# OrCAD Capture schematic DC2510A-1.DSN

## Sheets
1 PAGE2: size Custom
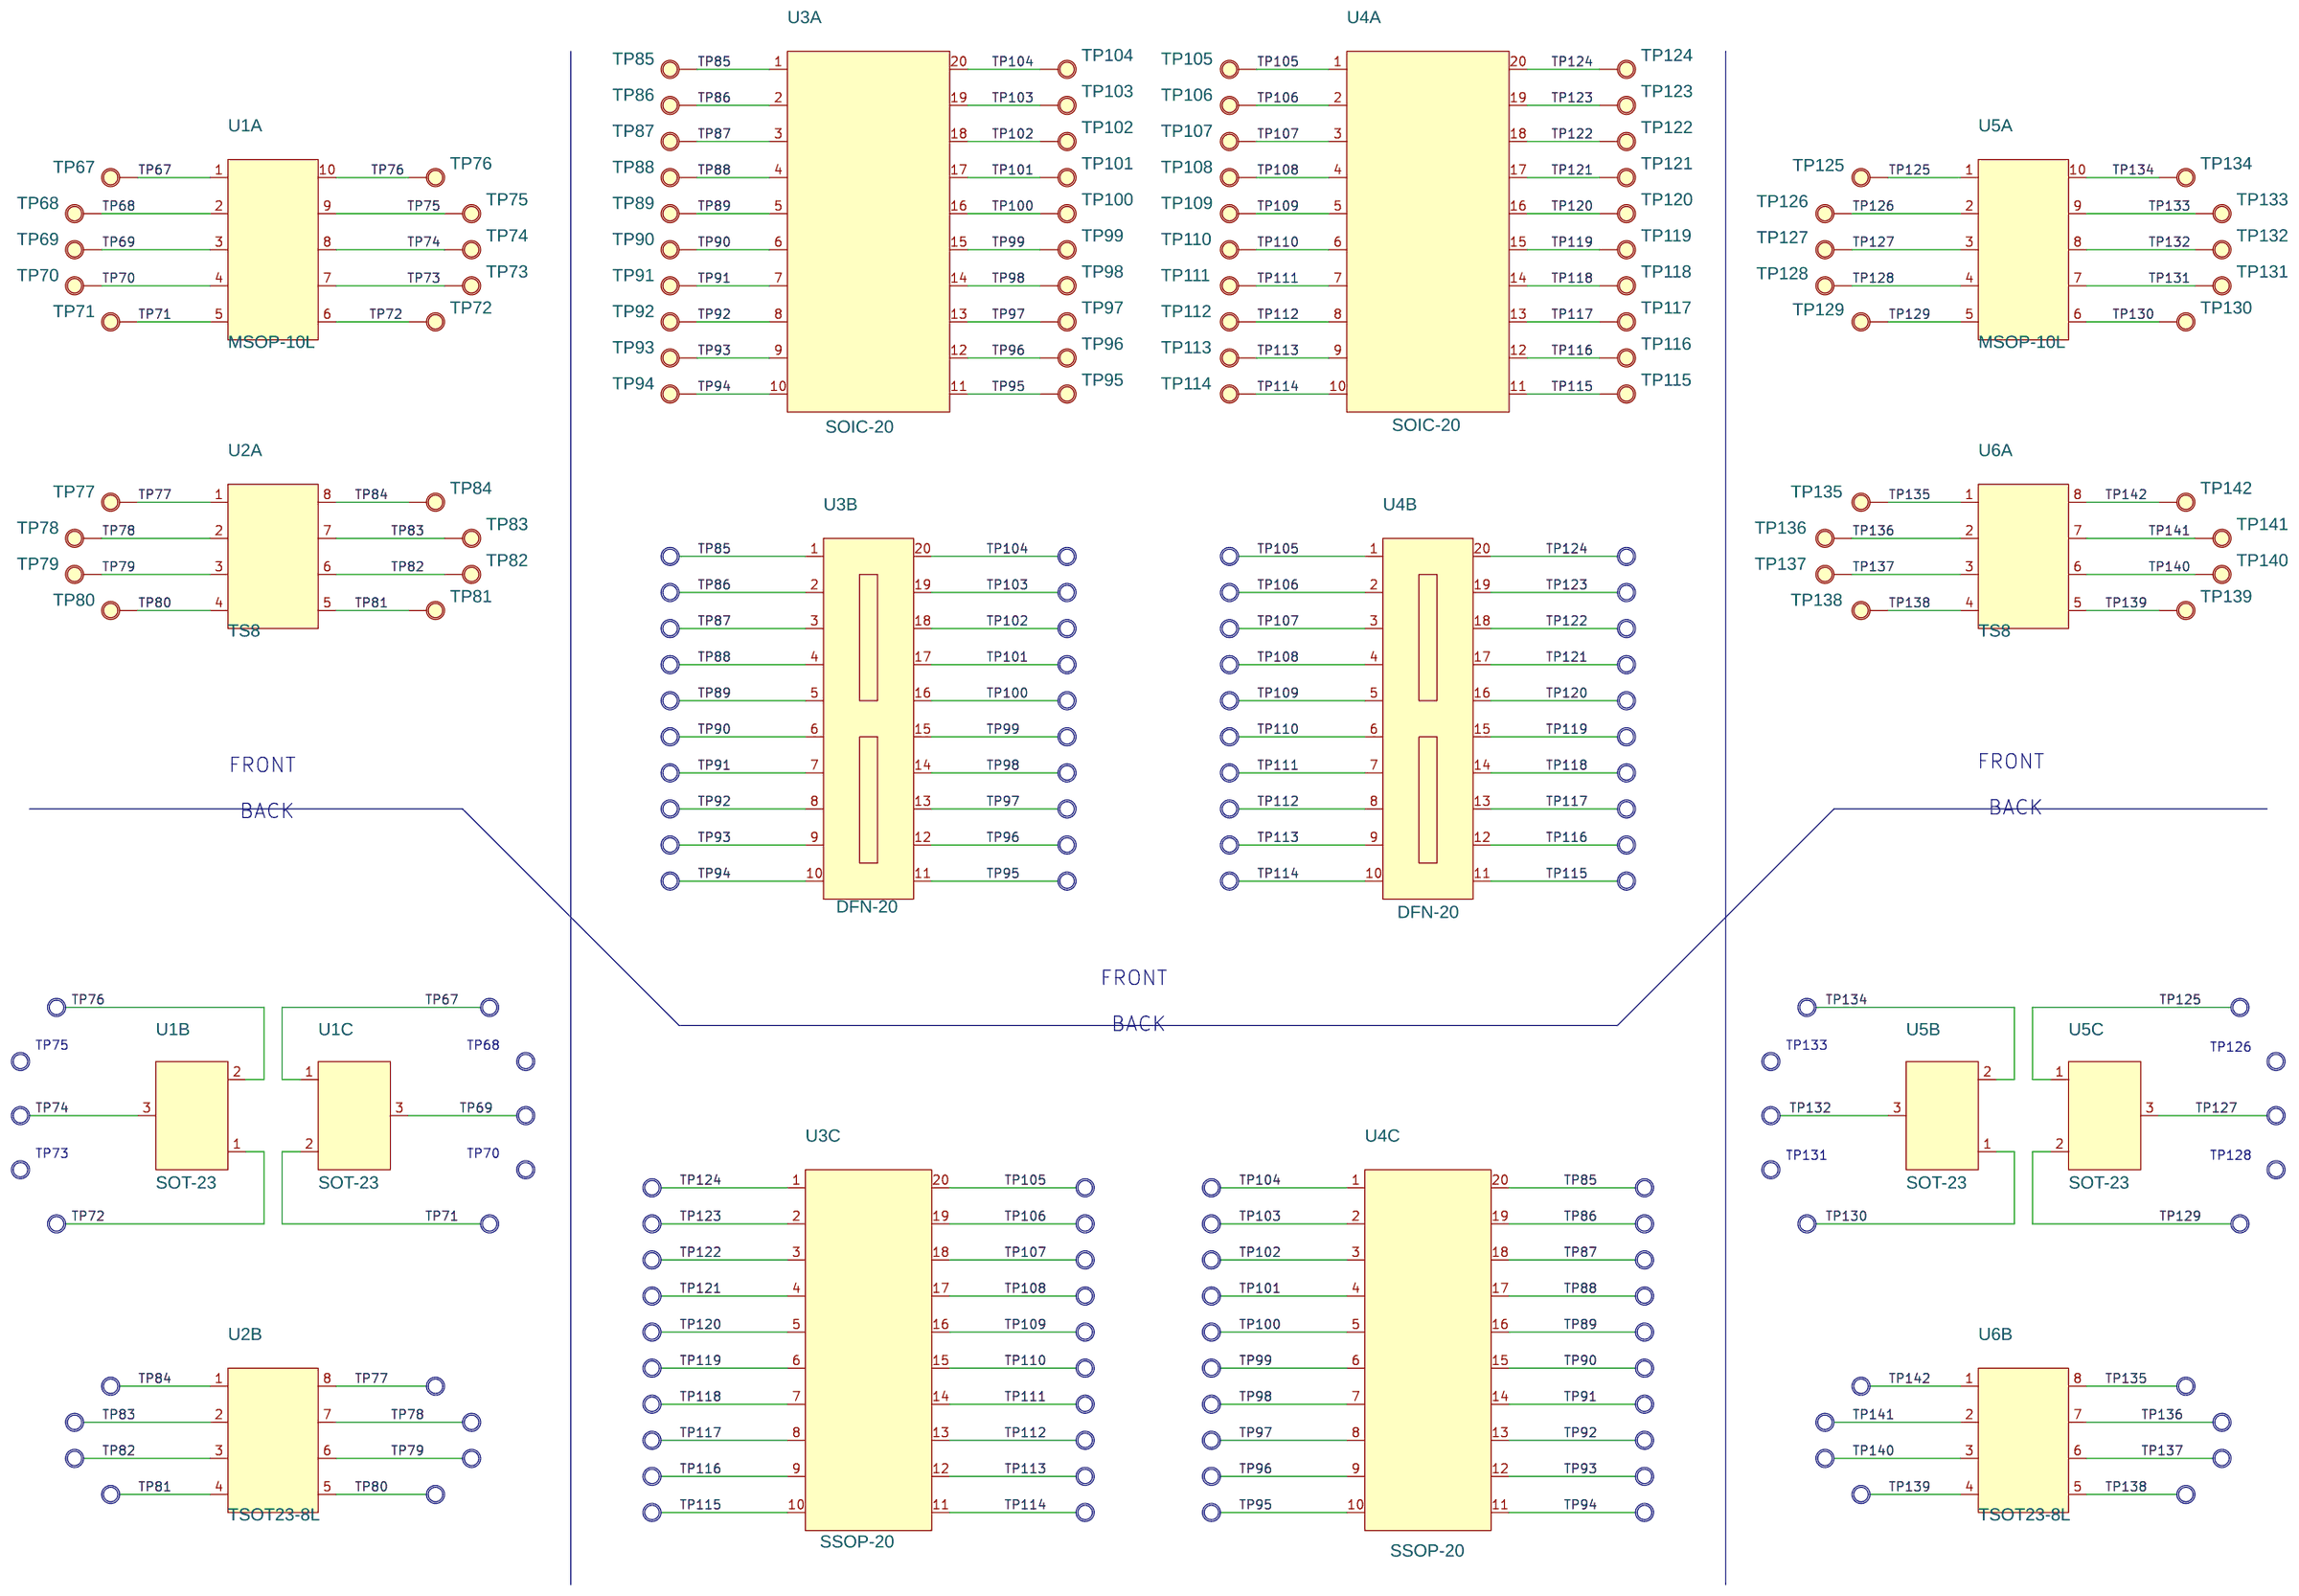
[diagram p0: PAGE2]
2 PAGE1: size Custom; title: DC2510A: SHIELD BOARD; rev: 1; note: DEMO CIRCUIT 2510A
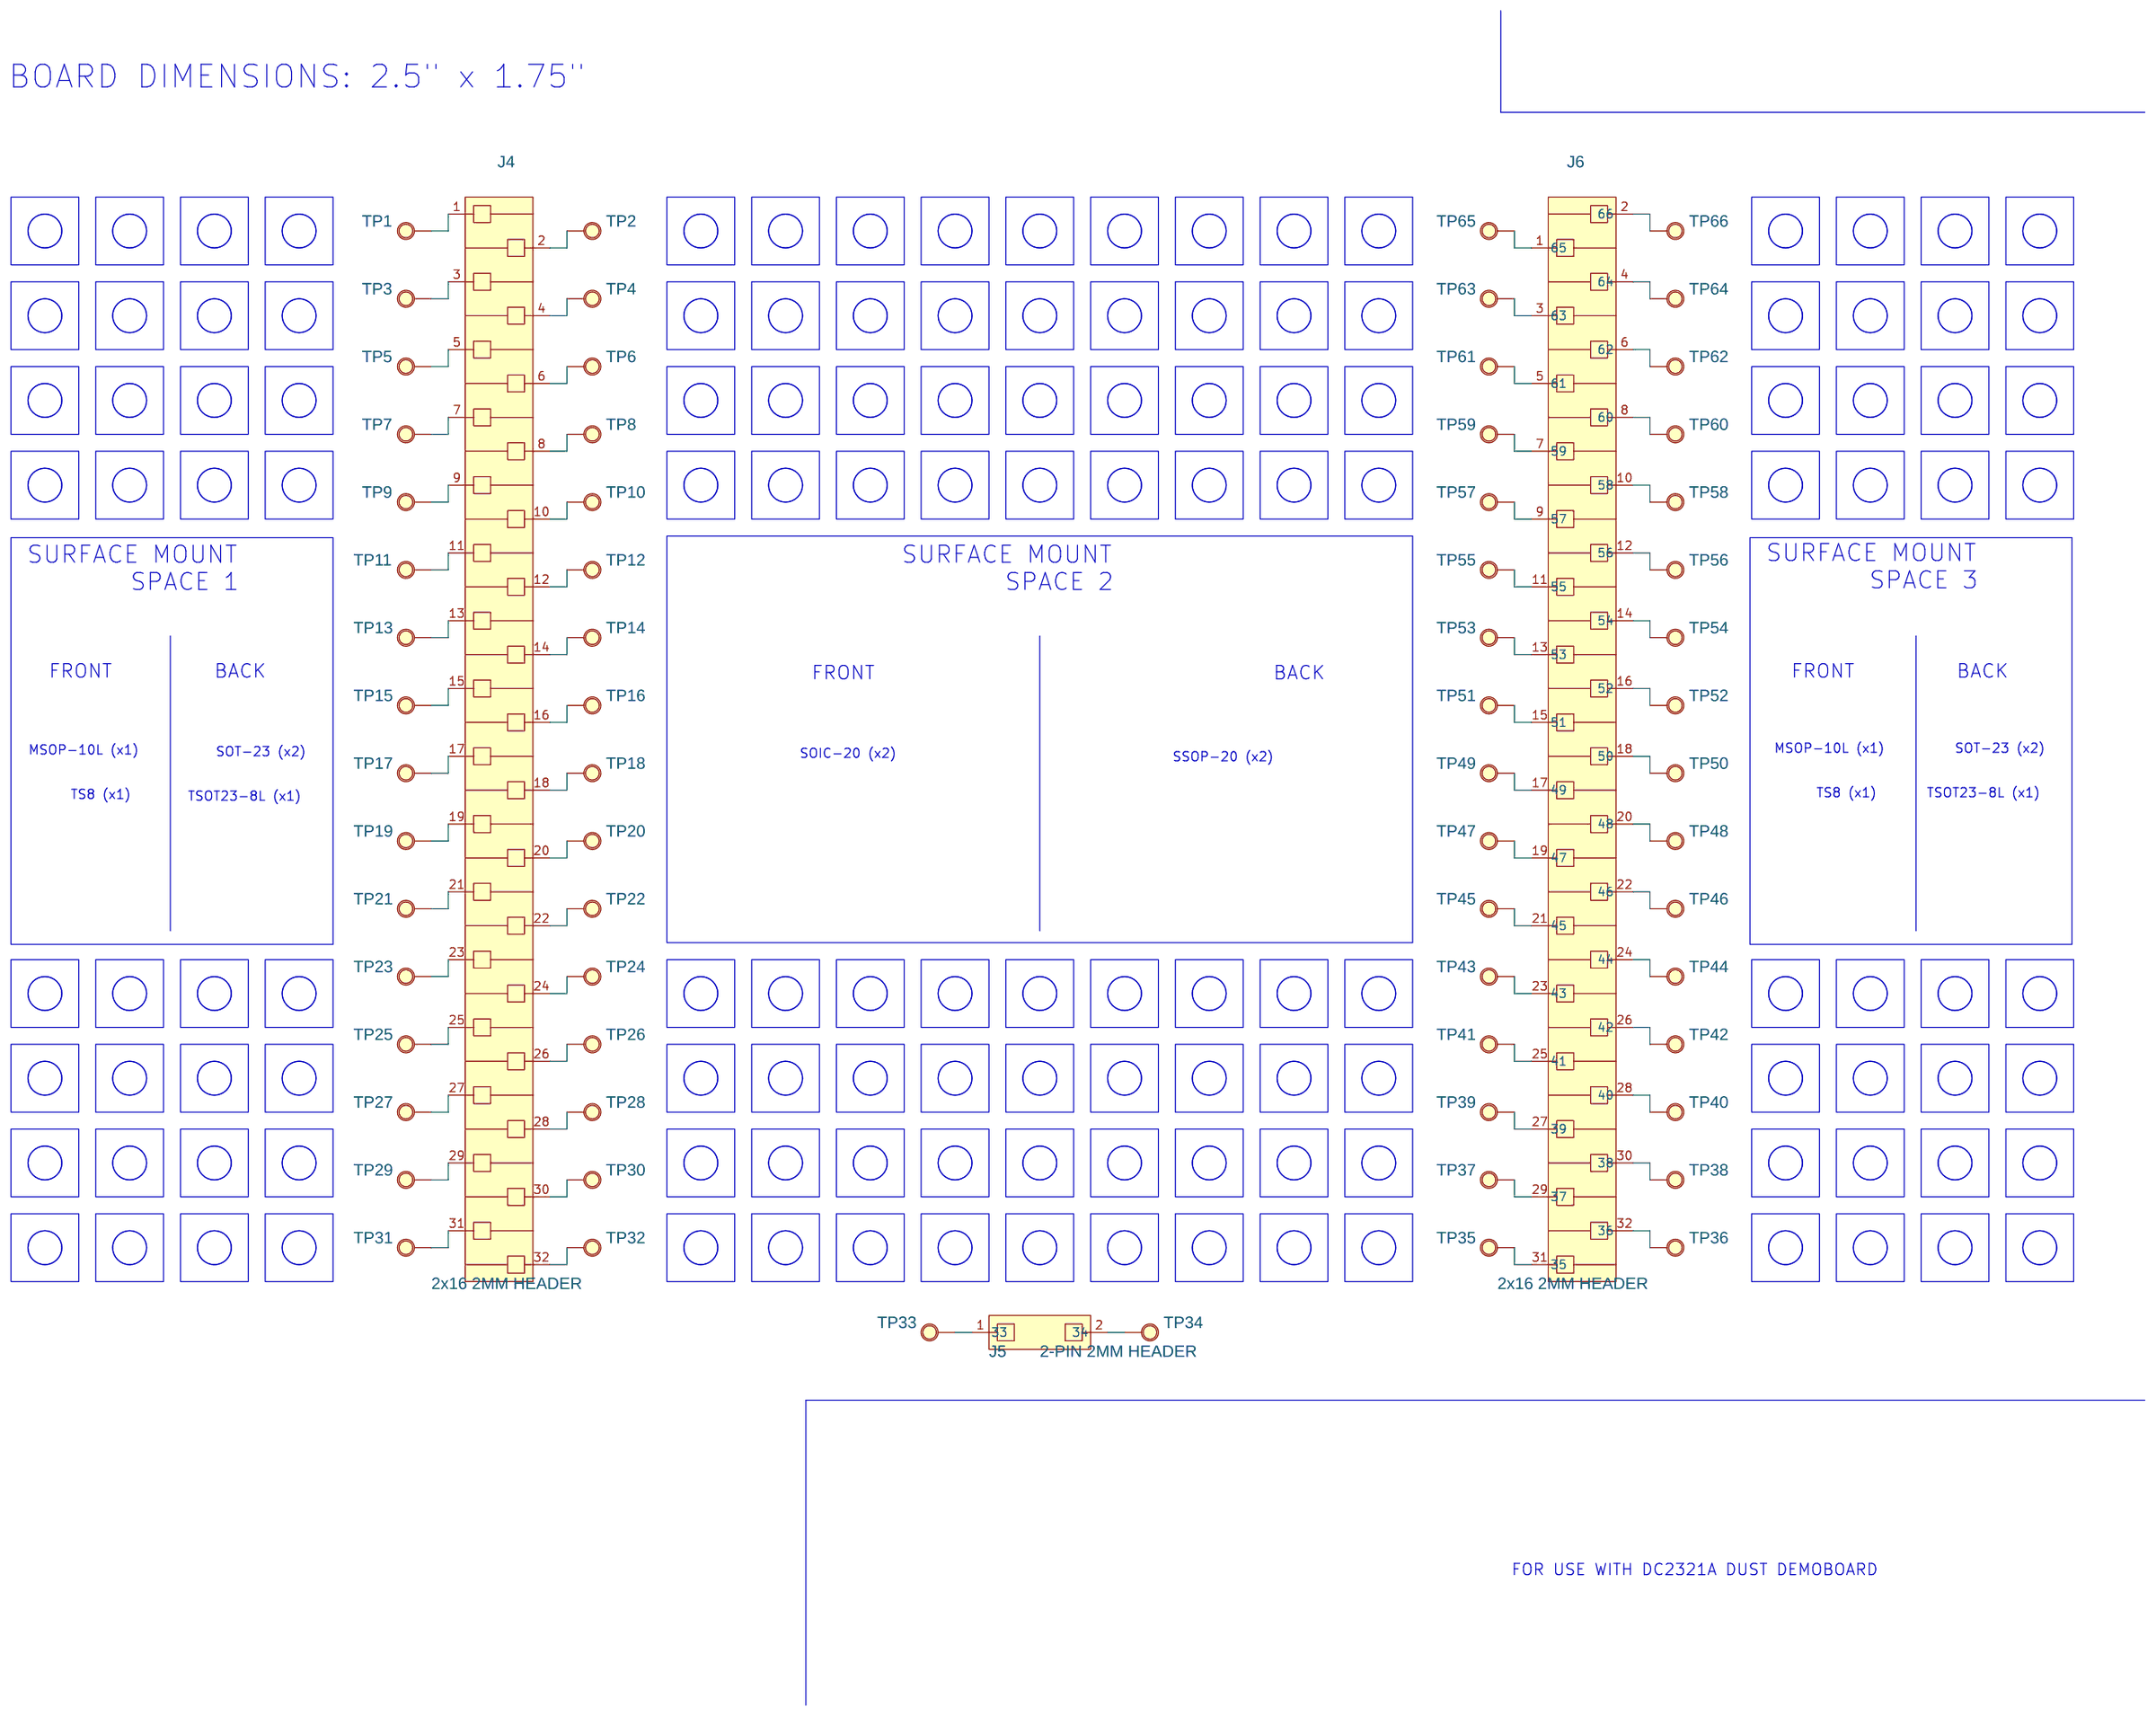
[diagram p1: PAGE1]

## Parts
sheet PAGE1
J4  2x16 2MM HEADER  [HDR-WURTH-62003221821-2X16-2MM]
J5  2-PIN 2MM HEADER  [WURTH-62000211821-2P-2MM]
J6  2x16 2MM HEADER  [HDR-WURTH-62003221821-2X16-2MM]
TP1  Large Turret_1  [TP]
TP2  Large Turret_1  [TP]
TP3  Large Turret_1  [TP]
TP4  Large Turret_1  [TP]
TP5  Large Turret_1  [TP]
TP6  Large Turret_1  [TP]
TP7  Large Turret_1  [TP]
TP8  Large Turret_1  [TP]
TP9  Large Turret_1  [TP]
TP10  Large Turret_1  [TP]
TP11  Large Turret_1  [TP]
TP12  Large Turret_1  [TP]
TP13  Large Turret_1  [TP]
TP14  Large Turret_1  [TP]
TP15  Large Turret_1  [TP]
TP16  Large Turret_1  [TP]
TP17  Large Turret_1  [TP]
TP18  Large Turret_1  [TP]
TP19  Large Turret_1  [TP]
TP20  Large Turret_1  [TP]
TP21  Large Turret_1  [TP]
TP22  Large Turret_1  [TP]
TP23  Large Turret_1  [TP]
TP24  Large Turret_1  [TP]
TP25  Large Turret_1  [TP]
TP26  Large Turret_1  [TP]
TP27  Large Turret_1  [TP]
TP28  Large Turret_1  [TP]
TP29  Large Turret_1  [TP]
TP30  Large Turret_1  [TP]
TP31  Large Turret_1  [TP]
TP32  Large Turret_1  [TP]
TP33  Large Turret_1  [TP]
TP34  Large Turret_1  [TP]
TP35  Large Turret_1  [TP]
TP36  Large Turret_1  [TP]
TP37  Large Turret_1  [TP]
TP38  Large Turret_1  [TP]
TP39  Large Turret_1  [TP]
TP40  Large Turret_1  [TP]
TP41  Large Turret_1  [TP]
TP42  Large Turret_1  [TP]
TP43  Large Turret_1  [TP]
TP44  Large Turret_1  [TP]
TP45  Large Turret_1  [TP]
TP46  Large Turret_1  [TP]
TP47  Large Turret_1  [TP]
TP48  Large Turret_1  [TP]
TP49  Large Turret_1  [TP]
TP50  Large Turret_1  [TP]
TP51  Large Turret_1  [TP]
TP52  Large Turret_1  [TP]
TP53  Large Turret_1  [TP]
TP54  Large Turret_1  [TP]
TP55  Large Turret_1  [TP]
TP56  Large Turret_1  [TP]
TP57  Large Turret_1  [TP]
TP58  Large Turret_1  [TP]
TP59  Large Turret_1  [TP]
TP60  Large Turret_1  [TP]
TP61  Large Turret_1  [TP]
TP62  Large Turret_1  [TP]
TP63  Large Turret_1  [TP]
TP64  Large Turret_1  [TP]
TP65  Large Turret_1  [TP]
TP66  Large Turret_1  [TP]
sheet PAGE2
TP67  Large Turret_1  [PAD060/035]
TP68  Large Turret_1  [PAD060/035]
TP69  Large Turret_1  [PAD060/035]
TP70  Large Turret_1  [PAD060/035]
TP71  Large Turret_1  [PAD060/035]
TP72  Large Turret_1  [PAD060/035]
TP73  Large Turret_1  [PAD060/035]
TP74  Large Turret_1  [PAD060/035]
TP75  Large Turret_1  [PAD060/035]
TP76  Large Turret_1  [PAD060/035]
TP77  Large Turret_1  [PAD060/035]
TP78  Large Turret_1  [PAD060/035]
TP79  Large Turret_1  [PAD060/035]
TP80  Large Turret_1  [PAD060/035]
TP81  Large Turret_1  [PAD060/035]
TP82  Large Turret_1  [PAD060/035]
TP83  Large Turret_1  [PAD060/035]
TP84  Large Turret_1  [PAD060/035]
TP85  Large Turret_1  [PAD060/035]
TP86  Large Turret_1  [PAD060/035]
TP87  Large Turret_1  [PAD060/035]
TP88  Large Turret_1  [PAD060/035]
TP89  Large Turret_1  [PAD060/035]
TP90  Large Turret_1  [PAD060/035]
TP91  Large Turret_1  [PAD060/035]
TP92  Large Turret_1  [PAD060/035]
TP93  Large Turret_1  [PAD060/035]
TP94  Large Turret_1  [PAD060/035]
TP95  Large Turret_1  [PAD060/035]
TP96  Large Turret_1  [PAD060/035]
TP97  Large Turret_1  [PAD060/035]
TP98  Large Turret_1  [PAD060/035]
TP99  Large Turret_1  [PAD060/035]
TP100  Large Turret_1  [PAD060/035]
TP101  Large Turret_1  [PAD060/035]
TP102  Large Turret_1  [PAD060/035]
TP103  Large Turret_1  [PAD060/035]
TP104  Large Turret_1  [PAD060/035]
TP105  Large Turret_1  [PAD060/035]
TP106  Large Turret_1  [PAD060/035]
TP107  Large Turret_1  [PAD060/035]
TP108  Large Turret_1  [PAD060/035]
TP109  Large Turret_1  [PAD060/035]
TP110  Large Turret_1  [PAD060/035]
TP111  Large Turret_1  [PAD060/035]
TP112  Large Turret_1  [PAD060/035]
TP113  Large Turret_1  [PAD060/035]
TP114  Large Turret_1  [PAD060/035]
TP115  Large Turret_1  [PAD060/035]
TP116  Large Turret_1  [PAD060/035]
TP117  Large Turret_1  [PAD060/035]
TP118  Large Turret_1  [PAD060/035]
TP119  Large Turret_1  [PAD060/035]
TP120  Large Turret_1  [PAD060/035]
TP121  Large Turret_1  [PAD060/035]
TP122  Large Turret_1  [PAD060/035]
TP123  Large Turret_1  [PAD060/035]
TP124  Large Turret_1  [PAD060/035]
TP125  Large Turret_1  [PAD060/035]
TP126  Large Turret_1  [PAD060/035]
TP127  Large Turret_1  [PAD060/035]
TP128  Large Turret_1  [PAD060/035]
TP129  Large Turret_1  [PAD060/035]
TP130  Large Turret_1  [PAD060/035]
TP131  Large Turret_1  [PAD060/035]
TP132  Large Turret_1  [PAD060/035]
TP133  Large Turret_1  [PAD060/035]
TP134  Large Turret_1  [PAD060/035]
TP135  Large Turret_1  [PAD060/035]
TP136  Large Turret_1  [PAD060/035]
TP137  Large Turret_1  [PAD060/035]
TP138  Large Turret_1  [PAD060/035]
TP139  Large Turret_1  [PAD060/035]
TP140  Large Turret_1  [PAD060/035]
TP141  Large Turret_1  [PAD060/035]
TP142  Large Turret_1  [PAD060/035]
U1A  MSOP-10L  [MSOP10]
U1B  SOT-23  [SOT-23]
U1C  SOT-23  [SOT-23]
U2A  TS8  [TS8]
U2B  TSOT23-8L  [TSOT23-8]
U3A  SOIC-20  [SOIC127P760X205-20L]
U3B  DFN-20  [DFN-CUSTOM-DC2510A]
U3C  SSOP-20  [SSOP20-2-MODIFIED]
U4A  SOIC-20  [SOIC127P760X205-20L]
U4B  DFN-20  [DFN-CUSTOM-DC2510A]
U4C  SSOP-20  [SSOP20-2-MODIFIED]
U5A  MSOP-10L  [MSOP10]
U5B  SOT-23  [SOT-23]
U5C  SOT-23  [SOT-23]
U6A  TS8  [TS8]
U6B  TSOT23-8L  [TSOT23-8]

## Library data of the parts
J4 = 2x16_2MM_CONNECTOR_19
J5 = 2_PIN,_2MM_PITCH,_SOCKET_9
J6 = 2x16_2MM_CONNECTOR_21
TP1-TP142 = Large_Turret_1
U1A U5A = LT1112_4
U1B U5B = LT1112_7
U1C U5C = LT1112_6
U2A U2B U6A U6B = LT1112_3
U3A = LT1112_12
U3B = LT1112_13
U3C U4C = LT1112_15
U4A = LT1112_11
U4B = LT1112_14

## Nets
TP67: TP67.1 U1A.1 U1C.1
TP68: TP68.1 U1A.2
TP69: TP69.1 U1A.3 U1C.3
TP70: TP70.1 U1A.4
TP71: TP71.1 U1A.5 U1C.2
TP72: TP72.1 U1A.6 U1B.1
TP73: TP73.1 U1A.7
TP74: TP74.1 U1A.8 U1B.3
TP75: TP75.1 U1A.9
TP76: TP76.1 U1A.10 U1B.2
TP77: TP77.1 U2A.1 U2B.8
TP78: TP78.1 U2A.2 U2B.7
TP79: TP79.1 U2A.3 U2B.6
TP80: TP80.1 U2A.4 U2B.5
TP81: TP81.1 U2A.5 U2B.4
TP82: TP82.1 U2A.6 U2B.3
TP83: TP83.1 U2A.7 U2B.2
TP84: TP84.1 U2A.8 U2B.1
TP85: TP85.1 U3A.1 U3B.1 U4C.20
TP86: TP86.1 U3A.2 U3B.2 U4C.19
TP87: TP87.1 U3A.3 U3B.3 U4C.18
TP88: TP88.1 U3A.4 U3B.4 U4C.17
TP89: TP89.1 U3A.5 U3B.5 U4C.16
TP90: TP90.1 U3A.6 U3B.6 U4C.15
TP91: TP91.1 U3A.7 U3B.7 U4C.14
TP92: TP92.1 U3A.8 U3B.8 U4C.13
TP93: TP93.1 U3A.9 U3B.9 U4C.12
TP94: TP94.1 U3A.10 U3B.10 U4C.11
TP95: TP95.1 U3A.11 U3B.11 U4C.10
TP96: TP96.1 U3A.12 U3B.12 U4C.9
TP97: TP97.1 U3A.13 U3B.13 U4C.8
TP98: TP98.1 U3A.14 U3B.14 U4C.7
TP99: TP99.1 U3A.15 U3B.15 U4C.6
TP100: TP100.1 U3A.16 U3B.16 U4C.5
TP101: TP101.1 U3A.17 U3B.17 U4C.4
TP102: TP102.1 U3A.18 U3B.18 U4C.3
TP103: TP103.1 U3A.19 U3B.19 U4C.2
TP104: TP104.1 U3A.20 U3B.20 U4C.1
TP105: TP105.1 U3C.20 U4A.1 U4B.1
TP106: TP106.1 U3C.19 U4A.2 U4B.2
TP107: TP107.1 U3C.18 U4A.3 U4B.3
TP108: TP108.1 U3C.17 U4A.4 U4B.4
TP109: TP109.1 U3C.16 U4A.5 U4B.5
TP110: TP110.1 U3C.15 U4A.6 U4B.6
TP111: TP111.1 U3C.14 U4A.7 U4B.7
TP112: TP112.1 U3C.13 U4A.8 U4B.8
TP113: TP113.1 U3C.12 U4A.9 U4B.9
TP114: TP114.1 U3C.11 U4A.10 U4B.10
TP115: TP115.1 U3C.10 U4A.11 U4B.11
TP116: TP116.1 U3C.9 U4A.12 U4B.12
TP117: TP117.1 U3C.8 U4A.13 U4B.13
TP118: TP118.1 U3C.7 U4A.14 U4B.14
TP119: TP119.1 U3C.6 U4A.15 U4B.15
TP120: TP120.1 U3C.5 U4A.16 U4B.16
TP121: TP121.1 U3C.4 U4A.17 U4B.17
TP122: TP122.1 U3C.3 U4A.18 U4B.18
TP123: TP123.1 U3C.2 U4A.19 U4B.19
TP124: TP124.1 U3C.1 U4A.20 U4B.20
TP125: TP125.1 U5A.1 U5C.1
TP126: TP126.1 U5A.2
TP127: TP127.1 U5A.3 U5C.3
TP128: TP128.1 U5A.4
TP129: TP129.1 U5A.5 U5C.2
TP130: TP130.1 U5A.6 U5B.1
TP131: TP131.1 U5A.7
TP132: TP132.1 U5A.8 U5B.3
TP133: TP133.1 U5A.9
TP134: TP134.1 U5A.10 U5B.2
TP135: TP135.1 U6A.1 U6B.8
TP136: TP136.1 U6A.2 U6B.7
TP137: TP137.1 U6A.3 U6B.6
TP138: TP138.1 U6A.4 U6B.5
TP139: TP139.1 U6A.5 U6B.4
TP140: TP140.1 U6A.6 U6B.3
TP141: TP141.1 U6A.7 U6B.2
TP142: TP142.1 U6A.8 U6B.1
N6751745: J4.5 TP5.1
N6751775: J4.6 TP6.1
N6751817: J4.7 TP7.1
N6751821: J4.8 TP8.1
N6751877: J4.9 TP9.1
N6751881: J4.10 TP10.1
N6751937: J4.11 TP11.1
N6751941: J4.12 TP12.1
N6752029: J4.13 TP13.1
N6752033: J4.14 TP14.1
N6752089: J4.15 TP15.1
N6752149: J4.17 TP17.1
N6752153: J4.18 TP18.1
N6752209: J4.19 TP19.1
N6752213: J4.20 TP20.1
N6752269: J4.21 TP21.1
N6752273: J4.22 TP22.1
N6752329: J4.23 TP23.1
N6752333: J4.24 TP24.1
N6752389: J4.25 TP25.1
N6752393: J4.26 TP26.1
N6752449: J4.27 TP27.1
N6752453: J4.28 TP28.1
N6752509: J4.29 TP29.1
N6752513: J4.30 TP30.1
N6752569: J4.31 TP31.1
N6752573: J4.32 TP32.1
N6752593: J4.2 TP2.1
N6752611: J4.1 TP1.1
N6752622: J4.4 TP4.1
N6752645: J4.3 TP3.1
N6753203: J6.31(35) TP35.1
N6753210: J6.32(36) TP36.1
N6753279: J6.29(37) TP37.1
N6753287: J6.30(38) TP38.1
N6753361: J6.27(39) TP39.1
N6753369: J6.28(40) TP40.1
N6753443: J6.25(41) TP41.1
N6753451: J6.26(42) TP42.1
N6753525: J6.23(43) TP43.1
N6753533: J6.24(44) TP44.1
N6753607: J6.21(45) TP45.1
N6753615: J6.22(46) TP46.1
N6753689: J6.19(47) TP47.1
N6753697: J6.20(48) TP48.1
N6753771: J6.17(49) TP49.1
N6753779: J6.18(50) TP50.1
N6753853: J6.15(51) TP51.1
N6753861: J6.16(52) TP52.1
N6753935: J6.13(53) TP53.1
N6753943: J6.14(54) TP54.1
N6754147: J6.11(55) TP55.1
N6754155: J6.12(56) TP56.1
N6754249: J6.9(57) TP57.1
N6754257: J6.10(58) TP58.1
N6754331: J6.7(59) TP59.1
N6754339: J6.8(60) TP60.1
N6754413: J6.5(61) TP61.1
N6754421: J6.6(62) TP62.1
N6754495: J6.3(63) TP63.1
N6754503: J6.4(64) TP64.1
N6754577: J6.1(65) TP65.1
N6754585: J6.2(66) TP66.1
N6754597: J5.1(33) TP33.1
N6754605: J5.2(34) TP34.1
N6768369: J4.16 TP16.1

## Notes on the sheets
sheet 1
- FRONT
   BACK
- FRONT
   BACK
- FRONT
   BACK
- TP75
- TP68
- TP133
- TP126
- TP73
- TP70
- TP131
- TP128
sheet 2
- BOARD DIMENSIONS: 2.5" x 1.75"
- SURFACE MOUNT
          SPACE 1
- SURFACE MOUNT
          SPACE 2
- SURFACE MOUNT
          SPACE 3
- FRONT          BACK
- FRONT                                       BACK
- FRONT          BACK
- MSOP-10L (x1)
        TS8 (x1)
- SOT-23 (x2)
  TSOT23-8L (x1)
- SOIC-20 (x2)
- SSOP-20 (x2)
- MSOP-10L (x1)
        TS8 (x1)
- SOT-23 (x2)
  TSOT23-8L (x1)
- FOR USE WITH DC2321A DUST DEMOBOARD
